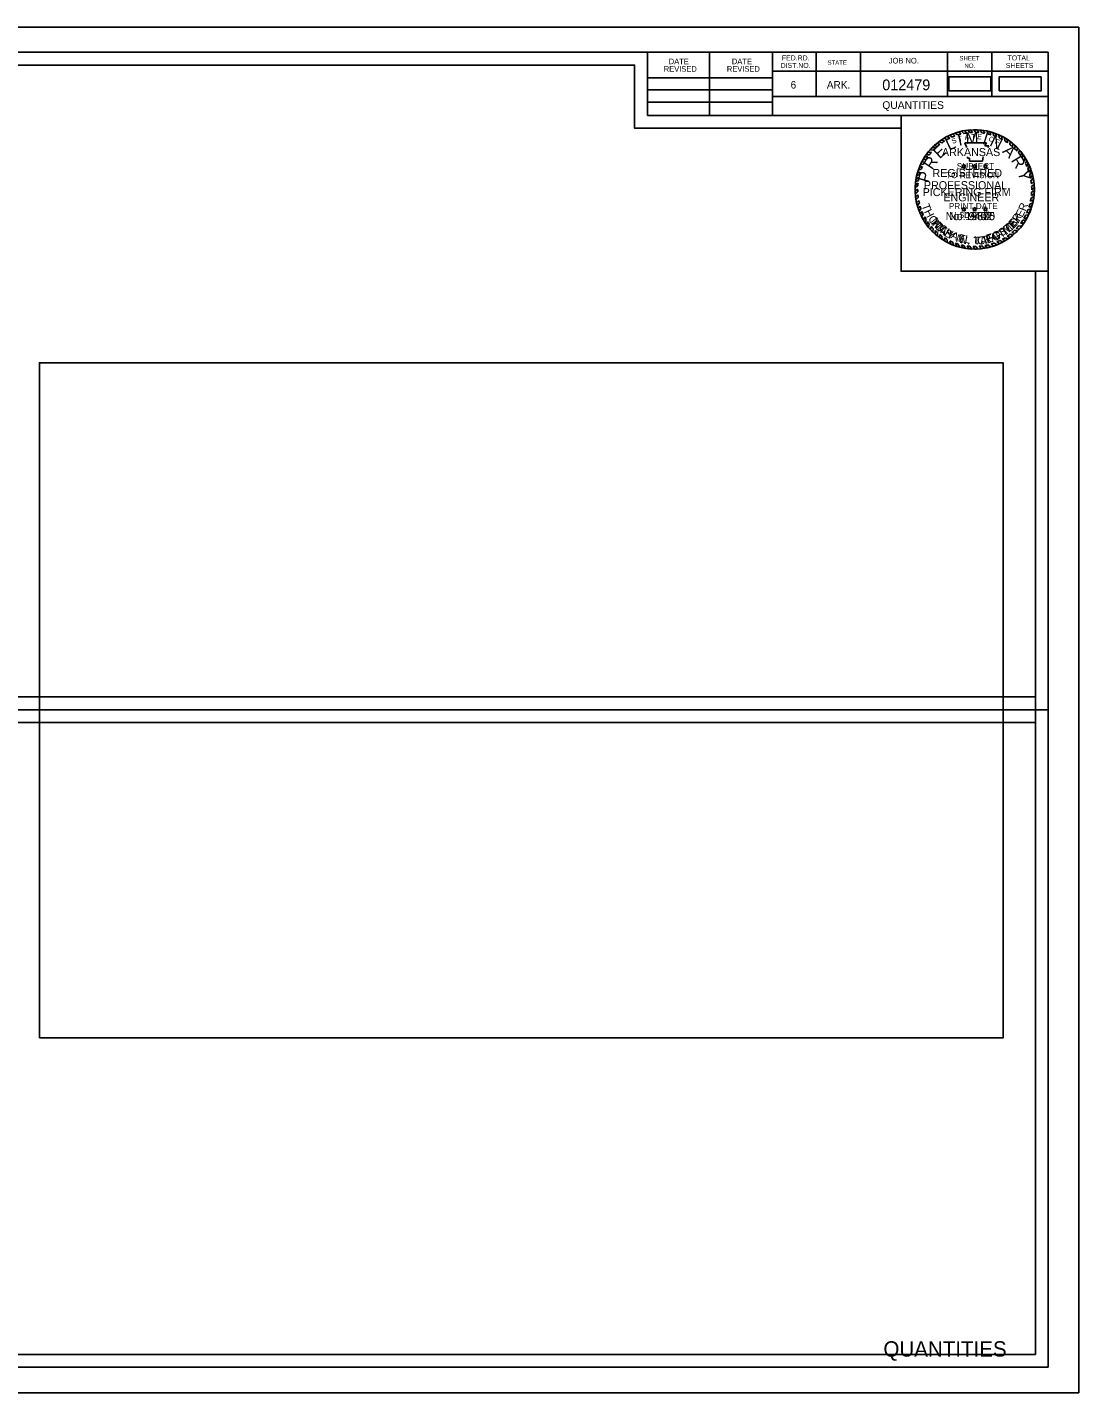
# Model space of a CAD drawing. Extents: x 1369290 to 1371547, y 379683 to 379897.
# Drawn here: x 1370555.2 to 1370719.5, y 379683.5 to 379896.8 of the extents above; entities that cross this region are included whole.
import ezdxf

# ---------------------------------------------------------------- set-up
doc = ezdxf.new("R2010")
doc.units = 0
for name, color, linetype in [('Default', 7, 'Continuous'), ('R_Border', 7, 'Continuous'), ('R_Border Notes', 7, 'Continuous'), ('R_Border Plan-Plan', 7, 'Continuous'), ('R_Border Title', 7, 'Continuous'), ('R_No Plot', 7, 'Continuous'), ('STAMP_PE_CRAFTON', 7, 'Continuous'), ('STAMP_PE_FOSTER', 7, 'Continuous'), ('STAMP_PE_SEAL-INFO', 7, 'Continuous'), ('STAMP_PE_TAEGTMEYER', 7, 'Continuous'), ('STAMP_PE_TXT', 7, 'Continuous'), ('STAMP_PRELIMINARY', 7, 'Continuous')]:
    doc.layers.add(name, color=color, linetype=linetype)

msp = doc.modelspace()

# ---------------------------------------------------------------- linework, layer by layer
at = {"layer": 'Default'}
for points in [[(1370699.16, 379886.89), (1370705.72, 379886.89), (1370705.72, 379889.08), (1370699.16, 379889.08)], [(1370707.03, 379886.89), (1370713.59, 379886.89), (1370713.59, 379889.08), (1370707.03, 379889.08)], [(1370557.07, 379738.92), (1370707.64, 379738.92), (1370707.64, 379844.4), (1370557.07, 379844.4)]]:
    msp.add_lwpolyline(points, close=True, dxfattribs=at)
at = {"layer": 'R_Border'}
for p, q in [((1370398.53, 379892.93), (1370714.71, 379892.93)), ((1370652.07, 379883.05), (1370652.07, 379892.93)), ((1370661.75, 379883.05), (1370661.75, 379892.93)), ((1370671.61, 379892.93), (1370671.61, 379883.05)), ((1370678.45, 379892.93), (1370678.45, 379885.99)), ((1370685.39, 379892.93), (1370685.39, 379885.99)), ((1370698.97, 379892.93), (1370698.97, 379885.99)), ((1370705.91, 379892.93), (1370705.91, 379885.99)), ((1370714.71, 379687.47), (1370714.71, 379892.93)), ((1370652.07, 379888.91), (1370671.61, 379888.91)), ((1370714.71, 379889.99), (1370671.61, 379889.99)), ((1370714.71, 379890.01), (1370714.71, 379890.01)), ((1370652.07, 379887.05), (1370671.61, 379887.05)), ((1370652.07, 379885.11), (1370671.61, 379885.11)), ((1370714.71, 379885.99), (1370671.61, 379885.99)), ((1370674.57, 379885.99), (1370714.71, 379885.99)), ((1370714.71, 379883.05), (1370652.07, 379883.05)), ((1370714.71, 379687.47), (1370398.53, 379687.47))]:
    msp.add_line(p, q, dxfattribs=at)
at = {"layer": 'R_Border Plan-Plan'}
msp.add_line((1370398.53, 379790.2), (1370714.71, 379790.2), dxfattribs=at)
at = {"layer": 'R_No Plot'}
for points in [[(1370386.12, 379896.82), (1370719.46, 379896.82), (1370719.46, 379683.48), (1370386.12, 379683.48)], [(1370712.71, 379792.2), (1370400.53, 379792.2), (1370400.53, 379890.93), (1370650.07, 379890.93), (1370650.07, 379881.05), (1370667.61, 379881.05), (1370691.71, 379881.05), (1370691.71, 379858.71), (1370712.71, 379858.71)], [(1370400.53, 379890.93), (1370650.07, 379890.93), (1370650.07, 379881.05), (1370667.61, 379881.05), (1370691.71, 379881.05), (1370691.71, 379858.71), (1370712.71, 379858.71), (1370712.71, 379689.47), (1370400.53, 379689.47)], [(1370691.71, 379883.05), (1370714.71, 379883.05), (1370714.71, 379858.71), (1370691.71, 379858.71)], [(1370400.53, 379788.2), (1370712.71, 379788.2), (1370712.71, 379689.47), (1370400.53, 379689.47)]]:
    msp.add_lwpolyline(points, close=True, dxfattribs=at)
at = {"layer": 'STAMP_PE_SEAL-INFO'}
for p, q in [((1370698.88, 379879.75), (1370699.34, 379879.52)), ((1370699.31, 379879.96), (1370699.7, 379879.68)), ((1370699.82, 379880.18), (1370700.11, 379879.85)), ((1370700.17, 379880.3), (1370700.55, 379880)), ((1370700.76, 379880.49), (1370701.05, 379880.14)), ((1370701.15, 379880.58), (1370701.5, 379880.24)), ((1370701.63, 379880.68), (1370701.93, 379880.31)), ((1370702.14, 379880.75), (1370702.43, 379880.37)), ((1370702.88, 379880.4), (1370702.57, 379880.79)), ((1370703.38, 379880.4), (1370703.1, 379880.81)), ((1370703.84, 379880.38), (1370703.58, 379880.81)), ((1370704.34, 379880.33), (1370704.05, 379880.77)), ((1370704.77, 379880.27), (1370704.51, 379880.72)), ((1370705.33, 379880.15), (1370705.16, 379880.61)), ((1370705.73, 379880.04), (1370705.57, 379880.51)), ((1370706.18, 379879.89), (1370706.04, 379880.37)), ((1370706.6, 379879.73), (1370706.46, 379880.23)), ((1370707.06, 379879.53), (1370706.96, 379880.02)), ((1370707.51, 379879.3), (1370707.42, 379879.81)), ((1370696.25, 379877.69), (1370696.77, 379877.65)), ((1370696.57, 379878.04), (1370697.11, 379877.99)), ((1370696.91, 379878.36), (1370697.36, 379878.22)), ((1370697.25, 379878.66), (1370697.78, 379878.56)), ((1370697.63, 379878.99), (1370698.08, 379878.78)), ((1370698.05, 379879.25), (1370698.49, 379879.05)), ((1370698.43, 379879.5), (1370698.87, 379879.27)), ((1370701.68, 379878.78), (1370705.03, 379878.78)), ((1370701.8, 379878.47), (1370701.68, 379878.78)), ((1370701.91, 379878.18), (1370701.8, 379878.47)), ((1370701.91, 379878.06), (1370701.91, 379878.18)), ((1370705.03, 379878.78), (1370704.8, 379878.29)), ((1370704.8, 379878.29), (1370705.43, 379878.29)), ((1370705.43, 379878.29), (1370705.29, 379878.06)), ((1370707.9, 379879.07), (1370707.86, 379879.57)), ((1370708.33, 379878.78), (1370708.3, 379879.3)), ((1370708.69, 379878.52), (1370708.73, 379879)), ((1370709.14, 379878.15), (1370709.16, 379878.67)), ((1370709.45, 379877.85), (1370709.52, 379878.35)), ((1370709.81, 379877.48), (1370709.88, 379878.01)), ((1370710.08, 379877.16), (1370710.22, 379877.63)), ((1370694.72, 379875.35), (1370695.23, 379875.46)), ((1370694.91, 379875.74), (1370695.41, 379875.81)), ((1370695.14, 379876.17), (1370695.63, 379876.19)), ((1370695.39, 379876.57), (1370695.9, 379876.6)), ((1370695.62, 379876.91), (1370696.13, 379876.91)), ((1370695.9, 379877.28), (1370696.45, 379877.3)), ((1370702.1, 379876.35), (1370702.08, 379876.57)), ((1370702.42, 379876.35), (1370702.1, 379876.35)), ((1370702.42, 379875.92), (1370702.42, 379876.35)), ((1370704.45, 379875.92), (1370702.42, 379875.92)), ((1370704.46, 379876.26), (1370704.45, 379875.92)), ((1370704.54, 379876.57), (1370704.46, 379876.26)), ((1370710.41, 379876.75), (1370710.54, 379877.25)), ((1370710.63, 379876.43), (1370710.8, 379876.89)), ((1370710.94, 379875.93), (1370711.12, 379876.42)), ((1370711.13, 379875.57), (1370711.36, 379876.01)), ((1370711.37, 379875.08), (1370711.59, 379875.57)), ((1370694.49, 379873.36), (1370694.03, 379873.11)), ((1370694.13, 379873.6), (1370694.6, 379873.8)), ((1370694.23, 379874.01), (1370694.71, 379874.18)), ((1370694.39, 379874.51), (1370694.87, 379874.65)), ((1370694.54, 379874.92), (1370695.04, 379875.07)), ((1370711.51, 379874.75), (1370711.77, 379875.18)), ((1370711.7, 379874.2), (1370711.97, 379874.67)), ((1370711.81, 379873.83), (1370712.1, 379874.28)), ((1370711.94, 379873.27), (1370712.26, 379873.72)), ((1370712.01, 379872.89), (1370712.36, 379873.25)), ((1370694.31, 379872.04), (1370693.89, 379871.78)), ((1370694.29, 379871.55), (1370693.89, 379871.21)), ((1370694.35, 379872.46), (1370693.91, 379872.18)), ((1370694.3, 379871.14), (1370693.91, 379870.81)), ((1370694.41, 379872.9), (1370693.96, 379872.68)), ((1370712.08, 379872.38), (1370712.45, 379872.72)), ((1370712.11, 379871.97), (1370712.5, 379872.26)), ((1370712.11, 379871.04), (1370712.53, 379871.32)), ((1370712.12, 379871.45), (1370712.53, 379871.77)), ((1370694.34, 379870.64), (1370693.96, 379870.29)), ((1370694.39, 379870.21), (1370694.03, 379869.84)), ((1370694.47, 379869.75), (1370694.13, 379869.39)), ((1370694.56, 379869.34), (1370694.25, 379868.92)), ((1370711.82, 379869.2), (1370712.29, 379869.4)), ((1370711.93, 379869.65), (1370712.38, 379869.84)), ((1370712.02, 379870.15), (1370712.46, 379870.37)), ((1370712.07, 379870.54), (1370712.5, 379870.79)), ((1370694.68, 379868.89), (1370694.39, 379868.47)), ((1370694.82, 379868.47), (1370694.54, 379868.05)), ((1370694.99, 379868.04), (1370694.73, 379867.62)), ((1370695.16, 379867.66), (1370694.93, 379867.19)), ((1370695.4, 379867.2), (1370695.21, 379866.71)), ((1370710.89, 379866.97), (1370711.39, 379867.03)), ((1370711.16, 379867.47), (1370711.65, 379867.54)), ((1370711.33, 379867.81), (1370711.81, 379867.9)), ((1370711.54, 379868.32), (1370712.02, 379868.45)), ((1370711.67, 379868.7), (1370712.16, 379868.9)), ((1370695.63, 379866.79), (1370695.45, 379866.32)), ((1370695.83, 379866.48), (1370695.72, 379865.93)), ((1370696.12, 379866.09), (1370696.01, 379865.56)), ((1370696.42, 379865.71), (1370696.33, 379865.19)), ((1370696.72, 379865.38), (1370696.66, 379864.85)), ((1370697.04, 379865.05), (1370697.01, 379864.52)), ((1370697.39, 379864.74), (1370697.39, 379864.21)), ((1370709.03, 379864.74), (1370709.5, 379864.61)), ((1370709.44, 379865.11), (1370709.88, 379864.97)), ((1370709.69, 379865.37), (1370710.17, 379865.29)), ((1370710.07, 379865.8), (1370710.53, 379865.73)), ((1370710.38, 379866.2), (1370710.89, 379866.2)), ((1370710.72, 379866.69), (1370711.2, 379866.69)), ((1370697.75, 379864.44), (1370697.77, 379863.92)), ((1370698.09, 379864.19), (1370698.12, 379863.68)), ((1370698.51, 379863.91), (1370698.57, 379863.4)), ((1370698.86, 379863.71), (1370698.96, 379863.19)), ((1370699.35, 379863.46), (1370699.5, 379862.94)), ((1370699.72, 379863.29), (1370699.89, 379862.78)), ((1370700.21, 379863.1), (1370700.42, 379862.59)), ((1370700.62, 379862.96), (1370700.85, 379862.47)), ((1370701.13, 379862.82), (1370701.34, 379862.36)), ((1370701.53, 379862.74), (1370701.77, 379862.28)), ((1370702.03, 379862.66), (1370702.27, 379862.21)), ((1370702.46, 379862.61), (1370702.74, 379862.18)), ((1370702.95, 379862.58), (1370703.25, 379862.17)), ((1370703.41, 379862.58), (1370703.75, 379862.18)), ((1370703.93, 379862.61), (1370704.25, 379862.23)), ((1370704.36, 379862.65), (1370704.74, 379862.29)), ((1370704.81, 379862.72), (1370705.2, 379862.38)), ((1370705.3, 379862.83), (1370705.68, 379862.5)), ((1370705.76, 379862.95), (1370706.18, 379862.65)), ((1370706.25, 379863.11), (1370706.7, 379862.84)), ((1370706.67, 379863.28), (1370707.1, 379863.02)), ((1370707.13, 379863.49), (1370707.62, 379863.28)), ((1370707.54, 379863.7), (1370707.96, 379863.47)), ((1370707.95, 379863.95), (1370708.4, 379863.75)), ((1370708.3, 379864.17), (1370708.74, 379863.98)), ((1370708.76, 379864.52), (1370709.23, 379864.37))]:
    msp.add_line(p, q, dxfattribs=at)
for radius, start, end in [(9.32, 117.6544, 120.8099), (9.32, 111.3124, 114.7026), (8.91, 110.3086, 113.1659), (9.32, 105.2339, 109.0352), (8.91, 104.0352, 107.3615), (9.32, 99.7525, 102.7765), (8.91, 98.258, 101.0329), (9.32, 93.9381, 96.5517), (8.91, 92.1102, 95.0367), (9.32, 87.7298, 90.6707), (8.91, 85.9628, 88.9097), (9.32, 81.9732, 84.8236), (8.91, 79.9264, 82.696), (9.32, 75.3125, 77.9426), (8.91, 73.5575, 76.2314), (9.32, 69.6061, 72.3058), (8.91, 67.6248, 70.504), (9.32, 63.1329, 66.2704), (9.32, 135.4021, 138.3031), (8.91, 133.1331, 136.2562), (9.32, 129.7326, 132.5376), (8.91, 127.5297, 130.9683), (9.32, 123.6199, 126.5906), (8.91, 121.9746, 125.11), (8.91, 115.6869, 119.1583), (8.91, 61.1558, 64.3784), (9.32, 56.9003, 60.0942), (8.91, 54.9238, 58.2702), (8.91, 48.3016, 52.0395), (9.32, 50.3492, 53.7159), (8.91, 42.2212, 45.5512), (9.32, 44.3405, 47.3929), (9.32, 38.1247, 41.2316), (9.32, 152.864, 155.5189), (9.32, 147.0072, 149.899), (8.91, 151.0315, 153.573), (9.32, 141.6056, 144.4486), (8.91, 145.0197, 148.2104), (8.91, 139.301, 142.5873), (8.91, 36.135, 39.5311), (8.91, 29.9032, 33.6645), (9.32, 31.9614, 35.4294), (8.91, 23.7732, 27.2211), (9.32, 25.9391, 29.0125), (9.32, 164.3068, 166.894), (9.32, 158.4077, 161.0701), (8.91, 167.9048, 170.9039), (8.91, 162.4331, 165.0013), (8.91, 156.3402, 159.2319), (8.91, 17.6802, 21.4251), (9.32, 19.9538, 23.3141), (8.91, 11.5444, 15.2364), (9.32, 13.8421, 17.4447), (9.32, 7.5852, 10.8621), (9.32, 175.7409, 178.2066), (9.32, 181.7251, 184.1626), (9.32, 170.0003, 172.6878), (8.91, 179.6454, 182.2633), (8.91, 173.73, 176.4734), (8.91, 5.7599, 9.0606), (8.91, 359.7329, 3.0639), (9.32, 1.7215, 4.7268), (9.32, 355.7156, 358.9569), (9.32, 187.4204, 190.1927), (9.32, 193.0369, 195.9973), (8.91, 185.4539, 188.234), (8.91, 191.2274, 193.9858), (8.91, 341.777, 345.0925), (8.91, 348.0778, 351.3435), (8.91, 353.8632, 357.1274), (9.32, 343.8925, 347.035), (9.32, 349.8305, 353.0885), (9.32, 198.8967, 201.6281), (8.91, 196.9675, 199.8353), (9.32, 204.5479, 207.4328), (8.91, 202.7761, 205.4791), (8.91, 208.7883, 211.7934), (8.91, 329.5549, 333.2076), (8.91, 335.6038, 339.1858), (9.32, 331.4037, 334.9332), (9.32, 337.3837, 340.9933), (9.32, 210.8636, 213.6571), (9.32, 216.6115, 219.491), (8.91, 214.1838, 217.2747), (9.32, 222.48, 225.3801), (8.91, 220.3909, 223.3056), (8.91, 226.2494, 229.2407), (8.91, 310.7744, 314.3161), (9.32, 312.4518, 315.6633), (8.91, 316.6531, 320.3711), (9.32, 318.2846, 321.8043), (8.91, 323.5851, 327.4407), (9.32, 325.4405, 328.9872), (9.32, 228.3665, 231.348), (8.91, 232.229, 234.9336), (9.32, 234.295, 236.9452), (8.91, 238.2223, 240.8353), (9.32, 240.1977, 242.8613), (8.91, 244.3204, 246.9486), (9.32, 246.576, 249.1558), (8.91, 250.3491, 253.1216), (9.32, 252.5967, 255.3252), (8.91, 256.505, 259.1192), (8.91, 262.3783, 265.2012), (8.91, 268.3215, 271.277), (8.91, 274.6157, 277.4486), (8.91, 280.3459, 283.5814), (8.91, 286.6423, 289.9783), (9.32, 288.5709, 291.9733), (8.91, 292.8745, 296.1185), (9.32, 294.6481, 298.2166), (8.91, 299.0768, 302.1724), (9.32, 300.621, 303.8703), (8.91, 304.823, 308.5143), (9.32, 306.3721, 310.208), (9.32, 258.4433, 261.1398), (9.32, 264.1978, 267.1009), (9.32, 270.2548, 273.3361), (9.32, 276.4239, 279.4357), (9.32, 282.3199, 285.3702)]:
    msp.add_arc((1370703.21, 379871.49), radius, start, end, dxfattribs=at)
at = {"layer": 'STAMP_PE_TXT'}
for p, q in [((1370701.43, 379875.21), (1370701.51, 379875.44)), ((1370701.51, 379875.44), (1370701.59, 379875.21)), ((1370703.13, 379875.21), (1370703.21, 379875.44)), ((1370703.21, 379875.44), (1370703.28, 379875.21)), ((1370704.83, 379875.21), (1370704.91, 379875.44)), ((1370704.91, 379875.44), (1370704.98, 379875.21)), ((1370701.39, 379875.06), (1370701.19, 379875.21)), ((1370701.19, 379875.21), (1370701.43, 379875.21)), ((1370701.31, 379874.83), (1370701.39, 379875.06)), ((1370701.51, 379874.97), (1370701.31, 379874.83)), ((1370701.71, 379874.83), (1370701.51, 379874.97)), ((1370701.59, 379875.21), (1370701.83, 379875.21)), ((1370701.83, 379875.21), (1370701.63, 379875.06)), ((1370701.63, 379875.06), (1370701.71, 379874.83)), ((1370703.09, 379875.06), (1370702.89, 379875.21)), ((1370702.89, 379875.21), (1370703.13, 379875.21)), ((1370703.01, 379874.83), (1370703.09, 379875.06)), ((1370703.21, 379874.97), (1370703.01, 379874.83)), ((1370703.41, 379874.83), (1370703.21, 379874.97)), ((1370703.28, 379875.21), (1370703.53, 379875.21)), ((1370703.53, 379875.21), (1370703.33, 379875.06)), ((1370703.33, 379875.06), (1370703.41, 379874.83)), ((1370704.78, 379875.06), (1370704.59, 379875.21)), ((1370704.59, 379875.21), (1370704.83, 379875.21)), ((1370704.71, 379874.83), (1370704.78, 379875.06)), ((1370704.91, 379874.97), (1370704.71, 379874.83)), ((1370705.1, 379874.83), (1370704.91, 379874.97)), ((1370704.98, 379875.21), (1370705.23, 379875.21)), ((1370705.23, 379875.21), (1370705.03, 379875.06)), ((1370705.03, 379875.06), (1370705.1, 379874.83)), ((1370701.39, 379868.35), (1370701.19, 379868.5)), ((1370701.19, 379868.5), (1370701.43, 379868.5)), ((1370701.31, 379868.12), (1370701.39, 379868.35)), ((1370701.51, 379868.27), (1370701.31, 379868.12)), ((1370701.43, 379868.5), (1370701.51, 379868.73)), ((1370701.51, 379868.73), (1370701.59, 379868.5)), ((1370701.71, 379868.12), (1370701.51, 379868.27)), ((1370701.59, 379868.5), (1370701.83, 379868.5)), ((1370701.83, 379868.5), (1370701.63, 379868.35)), ((1370701.63, 379868.35), (1370701.71, 379868.12)), ((1370703.09, 379868.35), (1370702.89, 379868.5)), ((1370702.89, 379868.5), (1370703.13, 379868.5)), ((1370703.01, 379868.12), (1370703.09, 379868.35)), ((1370703.21, 379868.27), (1370703.01, 379868.12)), ((1370703.13, 379868.5), (1370703.21, 379868.73)), ((1370703.21, 379868.73), (1370703.28, 379868.5)), ((1370703.41, 379868.12), (1370703.21, 379868.27)), ((1370703.28, 379868.5), (1370703.53, 379868.5)), ((1370703.53, 379868.5), (1370703.33, 379868.35)), ((1370703.33, 379868.35), (1370703.41, 379868.12)), ((1370704.78, 379868.35), (1370704.59, 379868.5)), ((1370704.59, 379868.5), (1370704.83, 379868.5)), ((1370704.71, 379868.12), (1370704.78, 379868.35)), ((1370704.91, 379868.27), (1370704.71, 379868.12)), ((1370704.83, 379868.5), (1370704.91, 379868.73)), ((1370704.91, 379868.73), (1370704.98, 379868.5)), ((1370705.1, 379868.12), (1370704.91, 379868.27)), ((1370704.98, 379868.5), (1370705.23, 379868.5)), ((1370705.23, 379868.5), (1370705.03, 379868.35)), ((1370705.03, 379868.35), (1370705.1, 379868.12))]:
    msp.add_line(p, q, dxfattribs=at)
at = {"layer": 'STAMP_PRELIMINARY'}
msp.add_circle((1370703.21, 379871.49), 9.32, dxfattribs=at)

# ---------------------------------------------------------------- texts
at = {"layer": 'R_Border'}
for s, height, p in [('FED.RD.', 0.782, (1370673.09, 379891.65)), ('TOTAL', 0.782, (1370708.35, 379891.65)), ('REVISED', 0.879, (1370654.63, 379889.88)), ('DATE', 0.879, (1370655.41, 379891.06)), ('REVISED', 0.879, (1370664.49, 379889.88)), ('DATE', 0.879, (1370665.27, 379891.06)), ('DIST.NO.', 0.782, (1370672.89, 379890.47)), ('STATE', 0.684, (1370680.21, 379890.97)), ('JOB NO.', 0.879, (1370689.79, 379891.17)), ('SHEET', 0.684, (1370700.83, 379891.65)), ('NO.', 0.684, (1370701.61, 379890.47)), ('SHEETS', 0.782, (1370708.07, 379890.47)), ('6', 1.17, (1370674.45, 379887.25)), ('ARK.', 1.172, (1370680.11, 379887.25))]:
    msp.add_text(s, height=height, dxfattribs=at).set_placement(p)
at = {"layer": 'R_Border Notes'}
for s, height, p in [('012479', 1.68, (1370688.77, 379886.99)), ('QUANTITIES', 1.2, (1370688.78, 379884.07))]:
    msp.add_text(s, height=height, dxfattribs=at).set_placement(p)
at = {"layer": 'R_Border Title'}
msp.add_text('QUANTITIES', height=2.4, dxfattribs=at).set_placement((1370688.95, 379689.12))
at = {"layer": 'STAMP_PE_CRAFTON'}
for s, rotation, p in [('T', 310.7442, (1370696.17, 379866.39)), ('N', 49.2411, (1370709.49, 379865.51)), ('O', 317.6422, (1370696.84, 379865.58)), ('N', 324.4537, (1370697.69, 379864.79)), ('Y', 331.1686, (1370698.72, 379864.08)), ('F', 28.7821, (1370706.87, 379863.62)), ('T', 34.1136, (1370707.78, 379864.13)), ('O', 41.8391, (1370708.64, 379864.73)), ('N', 347.4752, (1370700.77, 379863.16)), ('.', 356.8926, (1370702, 379862.88)), ('C', 6.0117, (1370703.68, 379862.83)), ('R', 14.8189, (1370704.78, 379862.95)), ('A', 20.5125, (1370705.89, 379863.25))]:
    msp.add_text(s, height=1.25, rotation=rotation, dxfattribs=at).set_placement(p)
msp.add_text('No. 12370', height=1.25, dxfattribs=at).set_placement((1370698.67, 379866.69))
at = {"layer": 'STAMP_PE_FOSTER'}
for s, rotation, p in [('M', 308.339, (1370696.32, 379866.51)), ('E', 46.9613, (1370709.21, 379865.48)), ('R', 54.5031, (1370709.93, 379866.3)), ('I', 314.1842, (1370697.12, 379865.57)), ('C', 319.8733, (1370697.48, 379865.22)), ('H', 327.7235, (1370698.41, 379864.48)), ('A', 335.7276, (1370699.39, 379863.9)), ('O', 23.719, (1370706.29, 379863.57)), ('S', 31.7234, (1370707.4, 379864.1)), ('T', 39.4194, (1370708.35, 379864.73)), ('E', 343.5779, (1370700.52, 379863.43)), ('L', 350.8115, (1370701.58, 379863.16)), ('L', 1.2666, (1370703.12, 379863)), ('.', 6.8035, (1370704.17, 379863.06)), ('F', 15.8691, (1370705.24, 379863.24))]:
    msp.add_text(s, height=1.2, rotation=rotation, dxfattribs=at).set_placement(p)
msp.add_text('No. 9402', height=1.25, dxfattribs=at).set_placement((1370699.19, 379866.69))
at = {"layer": 'STAMP_PE_TAEGTMEYER'}
for s, rotation, p in [('T', 289.646, (1370694.9, 379869)), ('R', 69.57, (1370711.15, 379868)), ('H', 296.7339, (1370695.26, 379868.02)), ('O', 303.7708, (1370695.86, 379866.91)), ('E', 46.8094, (1370709.25, 379865.27)), ('Y', 53.9986, (1370709.99, 379866.08)), ('E', 63.0984, (1370710.65, 379867.02)), ('M', 314.2033, (1370696.51, 379865.96)), ('A', 321.0594, (1370697.47, 379864.99)), ('S', 327.8239, (1370698.3, 379864.35)), ('G', 23.3052, (1370706.21, 379863.35)), ('T', 31.466, (1370707.31, 379863.84)), ('M', 39.3, (1370708.21, 379864.39)), ('N', 344.2727, (1370700.19, 379863.34)), ('.', 350.6464, (1370701.41, 379863.01)), ('T', 3.0061, (1370703.07, 379862.81)), ('A', 8.9826, (1370704.12, 379862.87)), ('E', 17.6836, (1370705.16, 379863.02))]:
    msp.add_text(s, height=1.25, rotation=rotation, dxfattribs=at).set_placement(p)
msp.add_text('No. 19605', height=1.25, dxfattribs=at).set_placement((1370698.67, 379866.69))
at = {"layer": 'STAMP_PE_TXT'}
for s, rotation, p in [('T', 16.311, (1370700.73, 379878.97)), ('A', 9.0679, (1370701.69, 379879.22)), ('T', 1.8248, (1370702.68, 379879.35)), ('E', 355.2002, (1370703.59, 379879.36)), ('O', 342.2506, (1370705.32, 379879.08)), ('S', 23.5541, (1370699.81, 379878.59)), ('F', 335.0075, (1370706.28, 379878.74))]:
    msp.add_text(s, height=0.781, rotation=rotation, dxfattribs=at).set_placement(p)
for s, p in [('ARKANSAS', (1370698.1, 379876.7)), ('REGISTERED', (1370696.62, 379873.43)), ('PROFESSIONAL', (1370695.28, 379871.53)), ('ENGINEER', (1370698.32, 379869.63))]:
    msp.add_text(s, height=1.25, dxfattribs=at).set_placement(p)
at = {"layer": 'STAMP_PRELIMINARY'}
for s, rotation, p in [('I', 12.5248, (1370700.75, 379878.28)), ('M', 3.1074, (1370701.84, 379878.59)), ('I', 342.3164, (1370704.31, 379878.65)), ('N', 333.9382, (1370705.42, 379878.38)), ('E', 42.3578, (1370697.73, 379876.19)), ('L', 25.513, (1370699.22, 379877.52)), ('A', 315.6579, (1370707.45, 379877.35)), ('R', 56.2292, (1370696.58, 379874.45)), ('R', 301.3831, (1370708.82, 379876.04)), ('P', 73.913, (1370696.03, 379872.43)), ('Y', 283.2593, (1370709.91, 379874.25))]:
    msp.add_text(s, height=1.8, rotation=rotation, dxfattribs=at).set_placement(p)
for s, height, p in [('SUBJECT', 0.96, (1370700.41, 379874.64)), ('TO REVISION', 0.96, (1370698.74, 379873.25)), ('PICKERING FIRM', 1.25, (1370695.08, 379870.45)), ('PRINT DATE', 0.96, (1370699.17, 379868.41)), ('$DATE$', 0.96, (1370700.84, 379867.02))]:
    msp.add_text(s, height=height, dxfattribs=at).set_placement(p)

doc.saveas('drawing.dxf')
